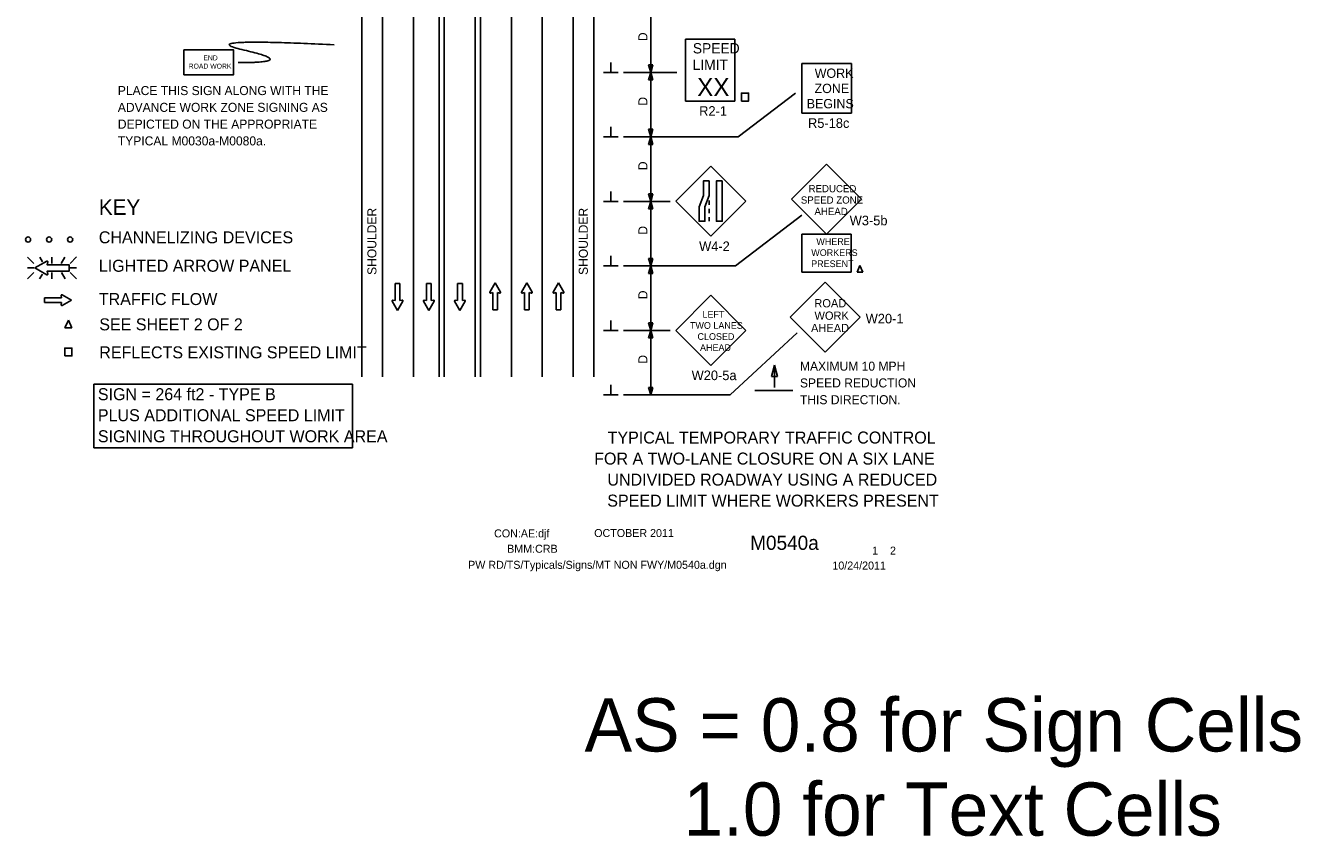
# Model space of a CAD drawing. Extents: x 16727 to 18475, y 5726 to 6927.
# Drawn here: x 16727 to 17716, y 5726 to 6355 of the extents above; entities that cross this region are included whole.
import ezdxf

# ---------------------------------------------------------------- set-up
doc = ezdxf.new("R2010")
doc.units = 0
for name, color, linetype in [('ALI_LEGAL_EX', 7, 'Continuous'), ('BORDER', 7, 'Continuous'), ('BORDER_SIGNAL_WO', 7, 'Continuous'), ('MT_SCRATCH_LEVEL_E', 7, 'Continuous'), ('PAVT_EDGE_EX', 7, 'Continuous'), ('TRAFFIC_SIGNS_PR', 7, 'Continuous'), ('TYPICAL_TEXT_DIMEN_EX', 7, 'Continuous'), ('TYPICAL_TEXT_DIMEN_PR', 7, 'Continuous')]:
    doc.layers.add(name, color=color, linetype=linetype)

msp = doc.modelspace()

# ---------------------------------------------------------------- linework, layer by layer
at = {"layer": 'ALI_LEGAL_EX'}
for p, q in [((17028.08, 6911.72), (17028.08, 6082.53)), ((17048.08, 6911.72), (17048.08, 6082.53)), ((17052.08, 6911.72), (17052.08, 6082.53)), ((17104.08, 6911.72), (17104.08, 6082.53)), ((17128.08, 6911.72), (17128.08, 6082.53)), ((17128.08, 6911.72), (17128.08, 6082.53))]:
    msp.add_line(p, q, dxfattribs=at)
for points in [[(17028.08, 6311.72), (17028.08, 6286.72)], [(17052.08, 6311.72), (17052.08, 6286.72)], [(17104.08, 6311.72), (17104.08, 6286.72)], [(17128.08, 6311.72), (17128.08, 6286.72)], [(17028.08, 6211.72), (17028.08, 6186.72)], [(17052.08, 6211.72), (17052.08, 6186.72)], [(17104.08, 6211.72), (17104.08, 6186.72)], [(17128.08, 6211.72), (17128.08, 6186.72)], [(17028.08, 6111.72), (17028.08, 6086.72)], [(17048.08, 6086.72), (17048.08, 6111.72)], [(17052.08, 6111.72), (17052.08, 6086.72)], [(17104.08, 6111.72), (17104.08, 6086.72)], [(17128.08, 6086.72), (17128.08, 6111.72)], [(17128.08, 6111.72), (17128.08, 6086.72)]]:
    msp.add_lwpolyline(points, dxfattribs=at)
at = {"layer": 'MT_SCRATCH_LEVEL_E'}
for p, q in [((17017.74, 6154.9), (17014, 6154.9)), ((17014, 6154.9), (17014, 6141.64)), ((17017.74, 6154.9), (17014, 6154.9)), ((17014, 6154.9), (17014, 6141.64)), ((17017.74, 6141.64), (17017.74, 6154.9)), ((17017.74, 6141.64), (17017.74, 6154.9)), ((17042, 6154.9), (17038.26, 6154.9)), ((17038.26, 6154.9), (17038.26, 6141.64)), ((17042, 6154.9), (17038.26, 6154.9)), ((17038.26, 6154.9), (17038.26, 6141.64)), ((17042, 6141.64), (17042, 6154.9)), ((17042, 6141.64), (17042, 6154.9)), ((17066.1, 6154.9), (17062.36, 6154.9)), ((17062.36, 6154.9), (17062.36, 6141.64)), ((17066.1, 6154.9), (17062.36, 6154.9)), ((17062.36, 6154.9), (17062.36, 6141.64)), ((17066.1, 6141.64), (17066.1, 6154.9)), ((17066.1, 6141.64), (17066.1, 6154.9)), ((17091.51, 6155.36), (17087.4, 6148.12)), ((17091.51, 6155.36), (17087.4, 6148.12)), ((17095.66, 6148.12), (17091.51, 6155.36)), ((17095.66, 6148.12), (17091.51, 6155.36)), ((17116.04, 6155.36), (17111.93, 6148.12)), ((17116.04, 6155.36), (17111.93, 6148.12)), ((17120.19, 6148.12), (17116.04, 6155.36)), ((17120.19, 6148.12), (17116.04, 6155.36)), ((17140.6, 6155.36), (17136.49, 6148.12)), ((17140.6, 6155.36), (17136.49, 6148.12)), ((17144.75, 6148.12), (17140.6, 6155.36)), ((17144.75, 6148.12), (17140.6, 6155.36)), ((16755.44, 6143.85), (16742.18, 6143.85)), ((16742.18, 6143.85), (16742.18, 6140.11)), ((16755.44, 6143.85), (16742.18, 6143.85)), ((16742.18, 6143.85), (16742.18, 6140.11)), ((16742.18, 6140.11), (16755.44, 6140.11)), ((16742.18, 6140.11), (16755.44, 6140.11)), ((16755.12, 6145.63), (16755.44, 6143.85)), ((16755.12, 6145.63), (16755.44, 6143.85)), ((16755.44, 6140.11), (16755.12, 6138.33)), ((16755.44, 6140.11), (16755.12, 6138.33)), ((16763.05, 6142), (16755.81, 6146.11)), ((16763.05, 6142), (16755.81, 6146.11)), ((16755.81, 6137.85), (16763.05, 6142)), ((16755.81, 6137.85), (16763.05, 6142)), ((17011.75, 6141.27), (17015.89, 6134.03)), ((17011.75, 6141.27), (17015.89, 6134.03)), ((17014, 6141.64), (17012.23, 6141.96)), ((17014, 6141.64), (17012.23, 6141.96)), ((17015.89, 6134.03), (17020, 6141.27)), ((17015.89, 6134.03), (17020, 6141.27)), ((17019.52, 6141.96), (17017.74, 6141.64)), ((17019.52, 6141.96), (17017.74, 6141.64)), ((17036, 6141.27), (17040.15, 6134.03)), ((17036, 6141.27), (17040.15, 6134.03)), ((17038.26, 6141.64), (17036.48, 6141.96)), ((17038.26, 6141.64), (17036.48, 6141.96)), ((17040.15, 6134.03), (17044.26, 6141.27)), ((17040.15, 6134.03), (17044.26, 6141.27)), ((17043.78, 6141.96), (17042, 6141.64)), ((17043.78, 6141.96), (17042, 6141.64)), ((17060.1, 6141.27), (17064.25, 6134.03)), ((17060.1, 6141.27), (17064.25, 6134.03)), ((17062.36, 6141.64), (17060.58, 6141.96)), ((17062.36, 6141.64), (17060.58, 6141.96)), ((17064.25, 6134.03), (17068.36, 6141.27)), ((17064.25, 6134.03), (17068.36, 6141.27)), ((17067.88, 6141.96), (17066.1, 6141.64)), ((17067.88, 6141.96), (17066.1, 6141.64)), ((17087.89, 6147.43), (17089.66, 6147.75)), ((17087.89, 6147.43), (17089.66, 6147.75)), ((17089.66, 6147.75), (17089.66, 6134.49)), ((17089.66, 6147.75), (17089.66, 6134.49)), ((17093.4, 6134.49), (17093.4, 6147.75)), ((17093.4, 6147.75), (17095.18, 6147.43)), ((17093.4, 6134.49), (17093.4, 6147.75)), ((17093.4, 6147.75), (17095.18, 6147.43)), ((17112.41, 6147.43), (17114.19, 6147.75)), ((17112.41, 6147.43), (17114.19, 6147.75)), ((17114.19, 6147.75), (17114.19, 6134.49)), ((17114.19, 6147.75), (17114.19, 6134.49)), ((17117.93, 6134.49), (17117.93, 6147.75)), ((17117.93, 6147.75), (17119.71, 6147.43)), ((17117.93, 6134.49), (17117.93, 6147.75)), ((17117.93, 6147.75), (17119.71, 6147.43)), ((17136.97, 6147.43), (17138.75, 6147.75)), ((17136.97, 6147.43), (17138.75, 6147.75)), ((17138.75, 6147.75), (17138.75, 6134.49)), ((17138.75, 6147.75), (17138.75, 6134.49)), ((17142.49, 6134.49), (17142.49, 6147.75)), ((17142.49, 6147.75), (17144.27, 6147.43)), ((17142.49, 6134.49), (17142.49, 6147.75)), ((17142.49, 6147.75), (17144.27, 6147.43)), ((17089.66, 6134.49), (17093.4, 6134.49)), ((17089.66, 6134.49), (17093.4, 6134.49)), ((17114.19, 6134.49), (17117.93, 6134.49)), ((17114.19, 6134.49), (17117.93, 6134.49)), ((17138.75, 6134.49), (17142.49, 6134.49)), ((17138.75, 6134.49), (17142.49, 6134.49))]:
    msp.add_line(p, q, dxfattribs=at)
for centre, start, end in [((17087.81, 6147.89), 150.42484, 279.96381), ((17087.81, 6147.89), 150.42484, 279.96381), ((17095.25, 6147.89), 260.03619, 29.77312), ((17095.25, 6147.89), 260.03619, 29.77312), ((17112.34, 6147.89), 150.42484, 279.96381), ((17112.34, 6147.89), 150.42484, 279.96381), ((17119.78, 6147.89), 260.03619, 29.77312), ((17119.78, 6147.89), 260.03619, 29.77312), ((17136.9, 6147.89), 150.42484, 279.96381), ((17136.9, 6147.89), 150.42484, 279.96381), ((17144.34, 6147.89), 260.03619, 29.77312), ((17144.34, 6147.89), 260.03619, 29.77312), ((16755.58, 6145.7), 60.42484, 189.96381), ((16755.58, 6145.7), 60.42484, 189.96381), ((16755.58, 6138.26), 170.03619, 299.77312), ((16755.58, 6138.26), 170.03619, 299.77312), ((17012.16, 6141.5), 80.03619, 209.77312), ((17012.16, 6141.5), 80.03619, 209.77312), ((17019.6, 6141.5), 330.42484, 99.96381), ((17019.6, 6141.5), 330.42484, 99.96381), ((17036.41, 6141.5), 80.03619, 209.77312), ((17036.41, 6141.5), 80.03619, 209.77312), ((17043.85, 6141.5), 330.42484, 99.96381), ((17043.85, 6141.5), 330.42484, 99.96381), ((17060.51, 6141.5), 80.03619, 209.77312), ((17060.51, 6141.5), 80.03619, 209.77312), ((17067.96, 6141.5), 330.42484, 99.96381), ((17067.96, 6141.5), 330.42484, 99.96381)]:
    msp.add_arc(centre, 0.463, start, end, dxfattribs=at)
at = {"layer": 'PAVT_EDGE_EX'}
for p, q in [((16988.08, 6923.5), (16988.08, 6082.53)), ((17004.08, 6923.5), (17004.08, 6082.53)), ((17076.08, 6923.5), (17076.08, 6082.53)), ((17080.08, 6923.5), (17080.08, 6082.53)), ((17152.08, 6923.5), (17152.08, 6082.53)), ((17168.08, 6923.5), (17168.08, 6082.53))]:
    msp.add_line(p, q, dxfattribs=at)
at = {"layer": 'TRAFFIC_SIGNS_PR'}
for p, q in [((17239, 6344.28), (17277.4, 6344.28)), ((17239, 6296.28), (17239, 6344.28)), ((17277.4, 6296.28), (17277.4, 6344.28)), ((17329.23, 6286.88), (17329.23, 6325.28)), ((17329.23, 6325.28), (17367.63, 6325.28)), ((17367.63, 6286.88), (17367.63, 6325.28)), ((17239, 6296.28), (17277.4, 6296.28)), ((17329.23, 6286.88), (17367.63, 6286.88)), ((17348.43, 6247.39), (17321.28, 6220.24)), ((17375.58, 6220.24), (17348.43, 6247.39)), ((17258.66, 6245.71), (17231.51, 6218.56)), ((17285.81, 6218.56), (17258.66, 6245.71)), ((17231.51, 6218.56), (17258.66, 6191.41)), ((17257.41, 6219.05), (17257.41, 6215.85)), ((17258.66, 6191.41), (17285.81, 6218.56)), ((17321.28, 6220.24), (17348.43, 6193.09)), ((17348.43, 6193.09), (17375.58, 6220.24)), ((17257.41, 6212.65), (17257.41, 6209.45)), ((17257.41, 6206.25), (17257.41, 6203.05)), ((17329.19, 6193.06), (17367.59, 6193.06)), ((17329.19, 6163.75), (17329.19, 6193.06)), ((17367.59, 6163.75), (17367.59, 6193.06)), ((16728.86, 6175.38), (16733.79, 6170.45)), ((16740.62, 6171.56), (16738.42, 6175.38)), ((16747.94, 6170.45), (16747.94, 6175.38)), ((16755.18, 6170.45), (16758.03, 6175.38)), ((16762.09, 6170.45), (16767.03, 6175.39)), ((16733.79, 6166.89), (16728.86, 6166.89)), ((16728.86, 6158.41), (16733.79, 6163.34)), ((16738.37, 6158.4), (16740.48, 6162.06)), ((16747.94, 6163.34), (16747.94, 6158.4)), ((16758.07, 6158.4), (16755.22, 6163.34)), ((16762.09, 6166.89), (16767.03, 6166.89)), ((16762.09, 6163.34), (16767.03, 6158.4)), ((17329.19, 6163.75), (17367.59, 6163.75)), ((17347.42, 6155.94), (17320.26, 6128.79)), ((17374.57, 6128.79), (17347.42, 6155.94)), ((17258.67, 6145.69), (17231.52, 6118.54)), ((17285.82, 6118.54), (17258.67, 6145.69)), ((17320.26, 6128.79), (17347.42, 6101.64)), ((17347.42, 6101.64), (17374.57, 6128.79)), ((17231.52, 6118.54), (17258.67, 6091.38)), ((17258.67, 6091.38), (17285.82, 6118.54))]:
    msp.add_line(p, q, dxfattribs=at)
for points in [[(16850.28, 6316.64), (16888.68, 6316.64), (16888.68, 6335.84), (16850.28, 6335.84)], [(17282.41, 6296.28), (17288.01, 6296.28), (17288.01, 6302.45), (17282.41, 6302.45)], [(17257.41, 6234.3), (17257.41, 6223.11), (17254.07, 6214.23), (17254.07, 6203.05), (17249.57, 6203.05), (17249.57, 6214.23), (17252.92, 6223.11), (17252.92, 6234.3)], [(17267.55, 6234.3), (17267.55, 6203.05), (17263.05, 6203.05), (17263.05, 6234.3)], [(16757.84, 6098.67), (16763.43, 6098.67), (16763.43, 6104.84), (16757.84, 6104.84)]]:
    msp.add_lwpolyline(points, close=True, dxfattribs=at)
for points in [[(16743.87, 6172.17), (16734.58, 6166.89), (16743.87, 6161.57)], [(16744.75, 6162.2), (16744.34, 6164.47), (16761.36, 6164.47), (16761.36, 6169.27), (16744.34, 6169.27), (16744.75, 6171.55)], [(17374.34, 6168.68), (17372.1, 6163.75)], [(17372.1, 6163.75), (17374.34, 6168.68)], [(17376.57, 6163.75), (17374.34, 6168.68)], [(17374.34, 6168.68), (17376.57, 6163.75)], [(17372.1, 6163.75), (17376.57, 6163.75)], [(17376.57, 6163.75), (17372.1, 6163.75)], [(16760.64, 6126.53), (16757.84, 6120.36)], [(16757.84, 6120.36), (16760.64, 6126.53)], [(16757.84, 6120.36), (16763.43, 6120.36)], [(16763.43, 6120.36), (16757.84, 6120.36)], [(16763.43, 6120.36), (16760.64, 6126.53)], [(16760.64, 6126.53), (16763.43, 6120.36)]]:
    msp.add_lwpolyline(points, dxfattribs=at)
for centre in [(16729.42, 6188.93), (16745.72, 6188.93), (16762.02, 6188.93)]:
    msp.add_circle(centre, 2, dxfattribs=at)
for centre, radius, start, end in [((16744.16, 6171.65), 0.598, 350.73078, 118.89165), ((16744.16, 6162.1), 0.597, 241.48329, 9.95933)]:
    msp.add_arc(centre, radius, start, end, dxfattribs=at)
msp.add_open_spline([(16892.27, 6326.02), (16939.51, 6326.02), (16854.48, 6345.37), (16966.78, 6339.88)], degree=2, dxfattribs=at)
at = {"layer": 'TYPICAL_TEXT_DIMEN_EX'}
msp.add_lwpolyline([(16780.5, 6076.81), (16980.88, 6076.81), (16980.88, 6027.57), (16780.5, 6027.57)], close=True, dxfattribs=at)
at = {"layer": 'TYPICAL_TEXT_DIMEN_PR'}
for p, q in [((17212.08, 6366.47), (17212.08, 6318.47)), ((17181.2, 6318.47), (17181.2, 6326.26)), ((17186.83, 6318.47), (17175.58, 6318.47)), ((17232.46, 6318.47), (17191.08, 6318.47)), ((17212.08, 6318.47), (17210.51, 6324.34)), ((17210.51, 6324.34), (17212.08, 6324.34)), ((17210.51, 6312.61), (17212.08, 6318.47)), ((17212.08, 6324.34), (17213.65, 6324.34)), ((17213.65, 6324.34), (17212.08, 6318.47)), ((17212.08, 6318.47), (17212.08, 6268.47)), ((17212.08, 6318.47), (17213.65, 6312.61)), ((17212.08, 6312.61), (17210.51, 6312.61)), ((17213.65, 6312.61), (17212.08, 6312.61)), ((17280, 6268.47), (17324.34, 6302.46)), ((17186.83, 6268.47), (17175.58, 6268.47)), ((17181.2, 6268.47), (17181.2, 6276.26)), ((17280, 6268.47), (17191.08, 6268.47)), ((17212.08, 6268.47), (17210.51, 6274.34)), ((17210.51, 6274.34), (17212.08, 6274.34)), ((17210.51, 6262.61), (17212.08, 6268.47)), ((17212.08, 6274.34), (17213.65, 6274.34)), ((17213.65, 6274.34), (17212.08, 6268.47)), ((17212.08, 6268.47), (17213.65, 6262.61)), ((17212.08, 6268.47), (17212.08, 6218.47)), ((17212.08, 6262.61), (17210.51, 6262.61)), ((17213.65, 6262.61), (17212.08, 6262.61)), ((17186.83, 6218.47), (17175.58, 6218.47)), ((17181.2, 6218.47), (17181.2, 6226.26)), ((17227.08, 6218.47), (17191.08, 6218.47)), ((17212.08, 6218.47), (17210.51, 6224.34)), ((17210.51, 6224.34), (17212.08, 6224.34)), ((17210.51, 6212.61), (17212.08, 6218.47)), ((17212.08, 6224.34), (17213.65, 6224.34)), ((17213.65, 6224.34), (17212.08, 6218.47)), ((17212.08, 6218.47), (17212.08, 6168.47)), ((17212.08, 6218.47), (17213.65, 6212.61)), ((17212.08, 6212.61), (17210.51, 6212.61)), ((17213.65, 6212.61), (17212.08, 6212.61)), ((17277.81, 6168.47), (17329.15, 6207.77)), ((17186.83, 6168.47), (17175.58, 6168.47)), ((17181.2, 6168.47), (17181.2, 6176.26)), ((17277.81, 6168.47), (17191.08, 6168.47)), ((17212.08, 6168.47), (17210.51, 6174.34)), ((17210.51, 6174.34), (17212.08, 6174.34)), ((17210.51, 6162.61), (17212.08, 6168.47)), ((17212.08, 6174.34), (17213.65, 6174.34)), ((17213.65, 6174.34), (17212.08, 6168.47)), ((17212.08, 6168.47), (17212.08, 6118.47)), ((17212.08, 6168.47), (17213.65, 6162.61)), ((17212.08, 6162.61), (17210.51, 6162.61)), ((17213.65, 6162.61), (17212.08, 6162.61)), ((17186.83, 6118.47), (17175.58, 6118.47)), ((17181.2, 6118.47), (17181.2, 6126.26)), ((17227.08, 6118.47), (17191.08, 6118.47)), ((17212.08, 6118.47), (17210.51, 6124.34)), ((17210.51, 6124.34), (17212.08, 6124.34)), ((17210.51, 6112.61), (17212.08, 6118.47)), ((17212.08, 6124.34), (17213.65, 6124.34)), ((17213.65, 6124.34), (17212.08, 6118.47)), ((17212.08, 6118.47), (17212.08, 6068.47)), ((17212.08, 6118.47), (17213.65, 6112.61)), ((17212.08, 6112.61), (17210.51, 6112.61)), ((17213.65, 6112.61), (17212.08, 6112.61)), ((17273.82, 6068.47), (17325.72, 6116.64)), ((17305.74, 6082.69), (17308.1, 6091.49)), ((17308.1, 6074.36), (17308.1, 6091.49)), ((17308.1, 6091.49), (17310.45, 6082.69)), ((17308.1, 6082.69), (17305.74, 6082.69)), ((17310.45, 6082.69), (17308.1, 6082.69)), ((17181.2, 6068.47), (17181.2, 6076.26)), ((17212.08, 6068.47), (17210.51, 6074.34)), ((17210.51, 6074.34), (17212.08, 6074.34)), ((17212.08, 6074.34), (17213.65, 6074.34)), ((17213.65, 6074.34), (17212.08, 6068.47)), ((17322.27, 6071.86), (17292.83, 6071.86)), ((17186.83, 6068.47), (17175.58, 6068.47)), ((17273.82, 6068.47), (17191.08, 6068.47))]:
    msp.add_line(p, q, dxfattribs=at)

# ---------------------------------------------------------------- texts
at = {"layer": 'BORDER'}
for s, p in [('TYPICAL TEMPORARY TRAFFIC CONTROL', (17178.7, 6030.8)), ('FOR A TWO-LANE CLOSURE ON A SIX LANE', (17168.28, 6014.5)), ('UNDIVIDED ROADWAY USING A REDUCED', (17178.52, 5998.2)), ('SPEED LIMIT WHERE WORKERS PRESENT', (17178.42, 5981.9))]:
    msp.add_text(s, height=9.3, dxfattribs=at).set_placement(p)
at = {"layer": 'BORDER_SIGNAL_WO'}
for s, height, p in [('CON:AE:djf', 6.2, (17090.69, 5958.06)), ('    OCTOBER 2011    ', 6.2, (17159.08, 5958.34)), ('BMM:CRB   ', 6.2, (17100.81, 5946.17)), ('    M0540a   ', 11, (17272.86, 5948.38)), (' 1    2 ', 6.2, (17381.45, 5944.7)), ('PW RD/TS/Typicals/Signs/MT NON FWY/M0540a.dgn    ', 6.2, (17070.55, 5933.71)), ('10/24/2011    ', 6.2, (17352.93, 5933.13)), ('AS = 0.8 for Sign Cells', 41.2877, (17160.83, 5792.11)), ('     1.0 for Text Cells', 41.2877, (17160.83, 5726.82))]:
    msp.add_text(s, height=height, dxfattribs=at).set_placement(p)
at = {"layer": 'TRAFFIC_SIGNS_PR'}
for s, height, p in [('SPEED', 8, (17244.76, 6333.14)), ('END', 3.831, (16865.28, 6327.78)), ('LIMIT', 8, (17244.6, 6320.34)), ('ROAD WORK', 3.831, (16853.89, 6321.39)), ('WORK', 7.217, (17339.23, 6314.24)), ('PLACE THIS SIGN ALONG WITH THE', 7, (16799, 6300.87)), ('XX', 14.031, (17248.11, 6300.04)), ('ZONE', 7.217, (17339.11, 6302.43)), ('BEGINS', 7.217, (17333.04, 6290.62)), ('ADVANCE WORK ZONE SIGNING AS', 7, (16799, 6287.87)), ('R2-1', 7.44, (17249.67, 6284.84)), ('DEPICTED ON THE APPROPRIATE', 7, (16799, 6274.87)), ('R5-18c', 7.44, (17334.04, 6275.44)), ('TYPICAL M0030a-M0080a.', 7, (16799, 6261.87)), ('REDUCED', 5.6, (17334.49, 6225.55)), ('SPEED ZONE', 5.6, (17328.48, 6216.75)), ('AHEAD', 5.6, (17339.04, 6207.95)), ('W3-5b', 7.44, (17366.36, 6199.97)), ('W4-2', 7.44, (17249.62, 6179.97)), ('WHERE', 5.2, (17340.5, 6184.75)), ('WORKERS', 5.2, (17336.57, 6176.15)), ('PRESENT', 5.2, (17336.5, 6167.55)), ('ROAD', 6.4, (17338.96, 6136.33)), ('LEFT', 5.2, (17252.2, 6128.32)), ('WORK', 6.4, (17339.07, 6126.73)), ('W20-1', 7.44, (17378.76, 6123.91)), ('TWO LANES', 5.2, (17242.53, 6119.72)), ('AHEAD', 6.4, (17336.38, 6117.13)), ('CLOSED', 5.2, (17248.38, 6111.12)), ('AHEAD', 5.2, (17250.33, 6102.52)), ('W20-5a', 7.44, (17243.81, 6079.94))]:
    msp.add_text(s, height=height, dxfattribs=at).set_placement(p)
at = {"layer": 'TYPICAL_TEXT_DIMEN_EX'}
for s, height, p in [('KEY', 12, (16784.26, 6208.03)), ('CHANNELIZING DEVICES', 9.3, (16784.26, 6185.98)), ('LIGHTED ARROW PANEL', 9.3, (16784.26, 6163.93)), ('TRAFFIC FLOW', 9.3, (16784.26, 6138.13)), ('SEE SHEET 2 OF 2', 9.3, (16784.61, 6118.53)), ('REFLECTS EXISTING SPEED LIMIT', 9.3, (16784.61, 6096.83)), ('SIGN = 264 ft2 - TYPE B', 9.3, (16783.52, 6064.4)), ('PLUS ADDITIONAL SPEED LIMIT', 9.3, (16783.52, 6048.1)), ('SIGNING THROUGHOUT WORK AREA', 9.3, (16783.52, 6031.8))]:
    msp.add_text(s, height=height, dxfattribs=at).set_placement(p)
at = {"layer": 'TYPICAL_TEXT_DIMEN_PR'}
for s, p in [('D', (17209.52, 6342.69)), ('D', (17209.52, 6292.69)), ('D', (17209.52, 6242.69)), ('SHOULDER', (16999.45, 6161.47)), ('SHOULDER', (17163.35, 6161.47)), ('D', (17209.52, 6192.69)), ('D', (17209.52, 6142.69)), ('D', (17209.52, 6092.69))]:
    msp.add_text(s, height=7, rotation=90, dxfattribs=at).set_placement(p)
for s, p in [('MAXIMUM 10 MPH', (17327.79, 6087.28)), ('SPEED REDUCTION', (17327.79, 6074.28)), ('THIS DIRECTION.', (17327.79, 6061.28))]:
    msp.add_text(s, height=7, dxfattribs=at).set_placement(p)

doc.saveas('drawing.dxf')
